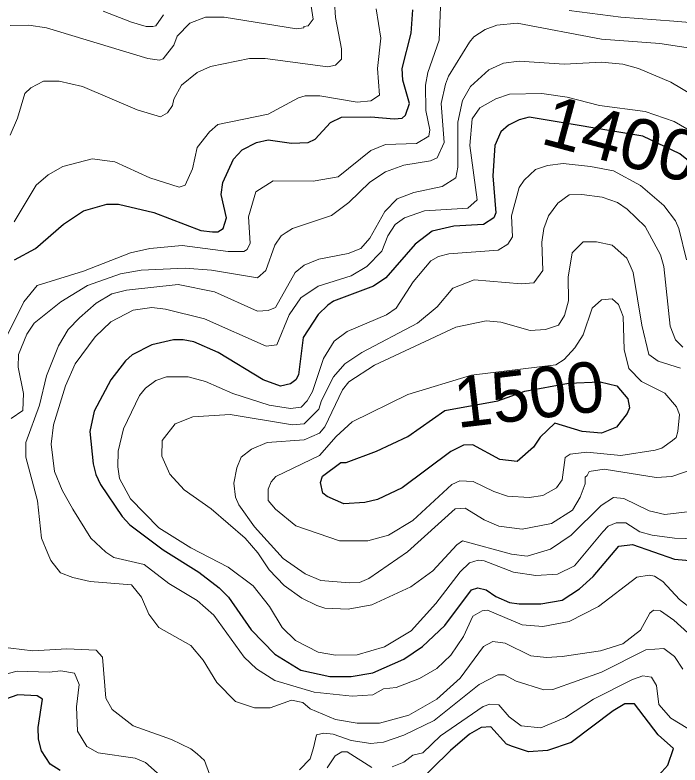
# Model space of a CAD drawing. Extents: x 423 to 448.8, y 7456.3 to 7484.
# Drawn here: x 432.428 to 433.481, y 7473.139 to 7474.327 of the extents above; entities that cross this region are included whole.
import ezdxf
from ezdxf.enums import TextEntityAlignment as Align

# ---------------------------------------------------------------- set-up
doc = ezdxf.new("R2010")
doc.units = 0
doc.header["$LTSCALE"] = 0.032
doc.layers.add('1', color=7, linetype='Continuous', lineweight=25)
doc.layers.add('2', color=7, linetype='Continuous', lineweight=13)
doc.layers.add('61', color=7, linetype='Continuous')

msp = doc.modelspace()

# ---------------------------------------------------------------- linework, layer by layer
at = {"layer": '1'}
for points in [[(432.741, 7473.9835), (432.7495, 7473.9835), (432.758, 7473.9889), (432.7634, 7474.0059), (432.7549, 7474.0431), (432.7572, 7474.0616), (432.7743, 7474.0987), (432.7882, 7474.1134), (432.8106, 7474.125), (432.8292, 7474.1297), (432.8663, 7474.1242), (432.8926, 7474.125), (432.9034, 7474.1304), (432.9281, 7474.1567), (432.9452, 7474.1653), (432.9916, 7474.166), (433.0287, 7474.1629), (433.0411, 7474.1637), (433.0465, 7474.1683), (433.0527, 7474.1869), (433.0426, 7474.224), (433.0411, 7474.2426), (433.0558, 7474.2983), (433.0581, 7474.3354)], [(433.4974, 7474.0941), (433.4812, 7474.1072), (433.4226, 7474.1353), (433.2422, 7474.1653), (433.2267, 7474.1614), (433.2097, 7474.1529), (433.1973, 7474.142), (433.188, 7474.1204), (433.1849, 7474.0725), (433.1896, 7474.0137), (433.1865, 7474.0059), (433.1703, 7473.9951), (433.1231, 7473.9928), (433.0891, 7473.985), (433.062, 7473.9642), (433.0156, 7473.9108), (432.9962, 7473.8976), (432.9328, 7473.8736), (432.9235, 7473.8675), (432.9081, 7473.8528), (432.8848, 7473.8164), (432.8771, 7473.7569), (432.8732, 7473.7491), (432.8647, 7473.743), (432.8485, 7473.7391), (432.8214, 7473.7491), (432.7502, 7473.7924), (432.7116, 7473.8095), (432.6946, 7473.8126), (432.6791, 7473.8126), (432.6451, 7473.8048), (432.6141, 7473.7886), (432.6033, 7473.7793), (432.5801, 7473.7491), (432.5538, 7473.6996), (432.5468, 7473.6672), (432.5523, 7473.6161), (432.5561, 7473.5991), (432.5639, 7473.5836), (432.5979, 7473.5326), (432.6103, 7473.5194), (432.6629, 7473.48), (432.7193, 7473.4444), (432.7518, 7473.4196), (432.7665, 7473.4049), (432.8021, 7473.3531), (432.84, 7473.3145), (432.881, 7473.2889), (432.9266, 7473.2789), (432.9607, 7473.2789), (432.9947, 7473.2851), (433.0442, 7473.3067), (433.0736, 7473.3268), (433.1091, 7473.3601), (433.1509, 7473.4165), (433.161, 7473.4196), (433.1741, 7473.4165), (433.1896, 7473.4057), (433.2113, 7473.3964), (433.2267, 7473.3941), (433.2608, 7473.3941), (433.2948, 7473.4003), (433.3219, 7473.4181), (433.3435, 7473.4374), (433.3845, 7473.4854), (433.4062, 7473.4885), (433.4727, 7473.4653), (433.5392, 7473.4591)], [(432.4277, 7473.9394), (432.461, 7473.9572), (432.5051, 7473.9958), (432.5368, 7474.0167), (432.5739, 7474.0276), (432.5925, 7474.0276), (432.6482, 7474.0144), (432.7224, 7473.9858), (432.741, 7473.9835)], [(432.4997, 7473.1304), (432.4842, 7473.1404), (432.4703, 7473.1613), (432.4656, 7473.1799), (432.4649, 7473.1984), (432.4718, 7473.2433), (432.4633, 7473.2487), (432.4331, 7473.2502), (432.4038, 7473.2402), (432.3295, 7473.2356), (432.311, 7473.2309), (432.2846, 7473.2177), (432.2615, 7473.1892), (432.2444, 7473.152), (432.2305, 7473.1334)], [(433.4479, 7473.1226), (433.4619, 7473.1389), (433.4711, 7473.1652), (433.4464, 7473.1868), (433.4093, 7473.2356), (433.3938, 7473.2356), (433.3752, 7473.2247), (433.3087, 7473.1744), (433.2716, 7473.1621), (433.2414, 7473.1598), (433.2159, 7473.1682), (433.2066, 7473.1721), (433.1818, 7473.1992), (433.1664, 7473.1984), (433.1478, 7473.1876), (433.1177, 7473.1621), (433.0589, 7473.104)]]:
    msp.add_lwpolyline(points, dxfattribs=at)
msp.add_lwpolyline([(433.0504, 7473.6594), (433.1091, 7473.7004), (433.1926, 7473.7159), (433.2357, 7473.731), (433.3049, 7473.744), (433.3549, 7473.7461), (433.3813, 7473.7396), (433.3984, 7473.719), (433.4015, 7473.705), (433.3977, 7473.6958), (433.3806, 7473.6741), (433.3567, 7473.6648), (433.3265, 7473.6671), (433.2832, 7473.6803), (433.26, 7473.6586), (433.2491, 7473.6424), (433.2236, 7473.6199), (433.1958, 7473.623), (433.1532, 7473.6462), (433.1386, 7473.6455), (433.1185, 7473.6354), (433.0411, 7473.5782), (433.0024, 7473.5596), (432.9823, 7473.555), (432.949, 7473.5526), (432.9228, 7473.5643), (432.9158, 7473.5697), (432.9119, 7473.5867), (432.915, 7473.5968), (432.9444, 7473.6184), (432.9529, 7473.6184), (433.0009, 7473.6362)], close=True, dxfattribs=at)
at = {"layer": '2'}
for points in [[(432.4208, 7474.3107), (432.4502, 7474.3114), (432.478, 7474.3068), (432.6389, 7474.2581), (432.6574, 7474.2557), (432.6629, 7474.258), (432.6799, 7474.2797), (432.6853, 7474.2937), (432.7054, 7474.3145), (432.7302, 7474.3238), (432.7596, 7474.3238), (432.874, 7474.3052), (432.8856, 7474.3068), (432.8856, 7474.3091), (432.8926, 7474.3099), (432.9003, 7474.3207), (432.888, 7474.4035)], [(432.4208, 7474.1366), (432.4324, 7474.1637), (432.444, 7474.2031), (432.4532, 7474.2116), (432.4734, 7474.2225), (432.4981, 7474.2225), (432.5353, 7474.214), (432.6219, 7474.1768), (432.659, 7474.166), (432.6698, 7474.1722), (432.6776, 7474.1838), (432.6799, 7474.1939), (432.6922, 7474.2163), (432.717, 7474.2364), (432.7379, 7474.2457), (432.7998, 7474.2581), (432.8245, 7474.2581), (432.9235, 7474.2449), (432.9359, 7474.248), (432.9452, 7474.2573), (432.9452, 7474.2736), (432.9359, 7474.3231), (432.9328, 7474.3726)], [(432.6636, 7474.3277), (432.6512, 7474.3099), (432.6466, 7474.3091), (432.6358, 7474.3091), (432.6126, 7474.3161), (432.5678, 7474.3331)], [(432.6111, 7473.9502), (432.642, 7473.9572), (432.6931, 7473.9618), (432.7658, 7473.9525), (432.7905, 7473.9525), (432.7959, 7473.9556), (432.8005, 7473.9657), (432.7982, 7474.0075), (432.8098, 7474.0469), (432.8369, 7474.0647), (432.9003, 7474.0639), (432.9398, 7474.0709), (432.9916, 7474.1126), (433.0148, 7474.1219), (433.0643, 7474.1235), (433.0836, 7474.1351), (433.0852, 7474.1452), (433.079, 7474.1761), (433.0782, 7474.2163), (433.0821, 7474.2364), (433.0999, 7474.2875), (433.1022, 7474.3401)], [(432.97, 7474.1892), (432.9916, 7474.1915), (433.0055, 7474.2), (433.0024, 7474.2426), (433.0078, 7474.2906), (433.0001, 7474.337)], [(433.3056, 7474.3346), (433.3876, 7474.3238), (433.4712, 7474.3176), (433.5547, 7474.3107)], [(433.1912, 7474.3114), (433.1726, 7474.3044), (433.1548, 7474.2929), (433.1478, 7474.2843), (433.1146, 7474.2302), (433.1099, 7474.2179), (433.103, 7474.1869), (433.1076, 7474.125), (433.0968, 7474.101), (433.086, 7474.0964), (433.0442, 7474.0895), (433.0148, 7474.0786), (432.9901, 7474.0624), (432.9568, 7474.0299), (432.9297, 7474.0098), (432.8679, 7473.9889), (432.8578, 7473.9827), (432.85, 7473.9773), (432.84, 7473.9626), (432.8253, 7473.9224), (432.8121, 7473.9108), (432.7395, 7473.9231), (432.6977, 7473.9262), (432.6281, 7473.9231), (432.5956, 7473.917), (432.543, 7473.8984), (432.5012, 7473.8729), (432.4587, 7473.8389), (432.4471, 7473.8218), (432.4339, 7473.7894), (432.4332, 7473.7693), (432.4416, 7473.7275), (432.4409, 7473.7004), (432.4223, 7473.688)], [(433.5114, 7474.2727), (433.4495, 7474.282), (433.3567, 7474.289), (433.2236, 7474.3145), (433.1912, 7474.3114)], [(433.5005, 7474.2008), (433.4665, 7474.2209), (433.4155, 7474.2426), (433.3907, 7474.2495), (433.3567, 7474.2527), (433.2979, 7474.2496), (433.2267, 7474.2542), (433.202, 7474.2511), (433.1788, 7474.2403), (433.1494, 7474.214), (433.137, 7474.1916), (433.1293, 7474.1575), (433.1293, 7474.0864), (433.1262, 7474.0693), (433.1045, 7474.0554), (433.0597, 7474.0461), (433.0334, 7474.0361), (433.014, 7474.016), (432.99, 7473.9734), (432.9761, 7473.9572), (432.956, 7473.9494), (432.9096, 7473.9402), (432.8864, 7473.9309), (432.8717, 7473.9193), (432.8408, 7473.8636), (432.8292, 7473.8589), (432.8121, 7473.8582), (432.7441, 7473.8884), (432.6869, 7473.9), (432.6049, 7473.8915), (432.5817, 7473.8853), (432.5569, 7473.8705), (432.5306, 7473.8473), (432.5128, 7473.8288), (432.4973, 7473.8033), (432.478, 7473.7553), (432.4672, 7473.7089), (432.4455, 7473.6501), (432.4455, 7473.6269), (432.4641, 7473.5573), (432.4703, 7473.4985), (432.4803, 7473.4738), (432.485, 7473.463), (432.5004, 7473.4436), (432.5198, 7473.4359), (432.5476, 7473.4297), (432.6126, 7473.4243), (432.6288, 7473.4049), (432.6404, 7473.3779), (432.6559, 7473.357), (432.707, 7473.3283), (432.7263, 7473.3052), (432.748, 7473.2696), (432.7773, 7473.2394), (432.8075, 7473.2293), (432.8323, 7473.2293), (432.8663, 7473.2417), (432.8841, 7473.2379), (432.8957, 7473.2278), (432.9359, 7473.2108), (432.97, 7473.2054), (433.0055, 7473.2054), (433.0519, 7473.2177), (433.096, 7473.2433), (433.1331, 7473.2765), (433.1702, 7473.3268), (433.185, 7473.3346), (433.2043, 7473.3322), (433.2453, 7473.3121), (433.2701, 7473.309), (433.2948, 7473.3106), (433.3551, 7473.3198), (433.3907, 7473.3307), (433.4186, 7473.3523), (433.4332, 7473.3794), (433.4394, 7473.384), (433.4502, 7473.3833), (433.4712, 7473.3686), (433.5214, 7473.3229)], [(432.4269, 7473.9997), (432.4618, 7474.0577), (432.4811, 7474.074), (432.5043, 7474.0871), (432.5507, 7474.0995), (432.5863, 7474.0948), (432.642, 7474.0694), (432.6884, 7474.0546), (432.6977, 7474.0577), (432.7093, 7474.0833), (432.717, 7474.1173), (432.7363, 7474.142), (432.7495, 7474.1536), (432.8292, 7474.1699), (432.8771, 7474.1962), (432.888, 7474.1993), (432.9112, 7474.1993), (432.97, 7474.1892)], [(433.5021, 7474.1413), (433.4721, 7474.1587), (433.4263, 7474.1745), (433.3536, 7474.1838), (433.3025, 7474.1969), (433.2623, 7474.2031), (433.2113, 7474.2016), (433.1896, 7474.1946), (433.1641, 7474.1799), (433.1524, 7474.1629), (433.1486, 7474.1204), (433.1602, 7474.0345), (433.1455, 7474.0214), (433.137, 7474.0206), (433.0767, 7474.0167), (433.045, 7474.0059), (433.0303, 7473.9951), (433.0186, 7473.9773), (433.0094, 7473.9533), (432.9854, 7473.9286), (432.9607, 7473.9139), (432.9081, 7473.8976), (432.881, 7473.8791), (432.8624, 7473.852), (432.8431, 7473.8048), (432.8261, 7473.8025), (432.7286, 7473.8458), (432.6668, 7473.8613), (432.6451, 7473.8636), (432.6157, 7473.8597), (432.5801, 7473.8412), (432.5553, 7473.8172), (432.5236, 7473.7746), (432.5082, 7473.7399), (432.4896, 7473.678), (432.4858, 7473.647), (432.4911, 7473.6037), (432.5028, 7473.5743), (432.5198, 7473.5442), (432.5484, 7473.4985), (432.5724, 7473.4761), (432.5848, 7473.4676), (432.6327, 7473.4567), (432.6721, 7473.4266), (432.717, 7473.3995), (432.7433, 7473.3763), (432.7913, 7473.3098), (432.8106, 7473.2912), (432.84, 7473.2727), (432.9019, 7473.2541), (432.9622, 7473.2479), (432.9947, 7473.2502), (433.0117, 7473.2595), (433.0318, 7473.2619), (433.069, 7473.2757), (433.096, 7473.292), (433.1184, 7473.3129), (433.1385, 7473.3423), (433.1532, 7473.3747), (433.168, 7473.3833), (433.1764, 7473.384), (433.2314, 7473.3608), (433.2639, 7473.3585), (433.3056, 7473.3662), (433.352, 7473.3903), (433.4131, 7473.4367), (433.4325, 7473.4397), (433.441, 7473.4382), (433.4541, 7473.4297), (433.4804, 7473.401), (433.5021, 7473.384)], [(433.4185, 7474.0569), (433.376, 7474.0802), (433.3397, 7474.0871), (433.2964, 7474.0918), (433.2716, 7474.0887), (433.2522, 7474.0825), (433.2344, 7474.0655), (433.2267, 7474.0538), (433.2144, 7474.009), (433.2159, 7473.9757), (433.2089, 7473.9642), (433.1934, 7473.9548), (433.1154, 7473.9487), (433.0991, 7473.9448), (433.0867, 7473.9378), (433.0589, 7473.9046), (433.0318, 7473.8628), (433.0163, 7473.852), (432.9545, 7473.8257), (432.9336, 7473.8102), (432.9166, 7473.7832), (432.8995, 7473.7306), (432.891, 7473.7159), (432.8817, 7473.7058), (432.8648, 7473.7035), (432.8307, 7473.7089), (432.7734, 7473.7274), (432.7302, 7473.7468), (432.7023, 7473.7538), (432.6683, 7473.7538), (432.6512, 7473.7483), (432.635, 7473.736), (432.6257, 7473.7244), (432.6002, 7473.6718), (432.5917, 7473.6362), (432.591, 7473.6115), (432.594, 7473.5929), (432.6111, 7473.5604), (432.6559, 7473.5148), (432.7069, 7473.4831), (432.7658, 7473.4521), (432.8052, 7473.4227), (432.8315, 7473.3903), (432.8516, 7473.357), (432.8725, 7473.3361), (432.9081, 7473.3175), (432.9359, 7473.3129), (432.97, 7473.3137), (433.0133, 7473.326), (433.0558, 7473.3516), (433.0945, 7473.3949), (433.1331, 7473.4451), (433.1478, 7473.4591), (433.1618, 7473.4637), (433.1711, 7473.4622), (433.2175, 7473.4444), (433.253, 7473.439), (433.2871, 7473.4413), (433.3141, 7473.4544), (433.359, 7473.5086), (433.3675, 7473.5171), (433.3799, 7473.5225), (433.3953, 7473.5225), (433.4178, 7473.5086), (433.4371, 7473.5031), (433.4727, 7473.4985), (433.5439, 7473.4962)], [(433.4913, 7473.9394), (433.4796, 7473.9889), (433.4742, 7474.0013), (433.4556, 7474.0252), (433.4185, 7474.0569)], [(433.2623, 7473.9673), (433.2654, 7473.9889), (433.2731, 7474.009), (433.2878, 7474.0291), (433.3056, 7474.0423), (433.3257, 7474.043), (433.3582, 7474.0384), (433.3822, 7474.0299), (433.3976, 7474.0198), (433.4263, 7473.992), (433.4502, 7473.9472), (433.4557, 7473.9286), (433.4657, 7473.8342), (433.4742, 7473.8126), (433.4858, 7473.8009)], [(432.9932, 7473.3925), (432.956, 7473.3856), (432.9189, 7473.3872), (432.9065, 7473.3918), (432.8825, 7473.4034), (432.8547, 7473.4235), (432.8307, 7473.4482), (432.8129, 7473.4753), (432.7928, 7473.4985), (432.7387, 7473.5449), (432.6961, 7473.5751), (432.6737, 7473.5998), (432.6606, 7473.6285), (432.6613, 7473.6532), (432.6822, 7473.6795), (432.71, 7473.6904), (432.7689, 7473.6942), (432.8679, 7473.6779), (432.8864, 7473.6795), (432.9096, 7473.7027), (432.9135, 7473.7167), (432.9328, 7473.7538), (432.9506, 7473.7747), (432.9776, 7473.7925), (433.0658, 7473.8388), (433.0968, 7473.8651), (433.1215, 7473.8945), (433.1556, 7473.9077), (433.2298, 7473.9015), (433.2499, 7473.903), (433.2638, 7473.9224), (433.2623, 7473.9673)], [(433.482, 7473.7677), (433.4464, 7473.7785), (433.4317, 7473.7894), (433.4208, 7473.8358), (433.4069, 7473.9193), (433.4023, 7473.9301), (433.3969, 7473.9417), (433.3737, 7473.9626), (433.3489, 7473.968), (433.328, 7473.968), (433.3103, 7473.9502), (433.304, 7473.9116), (433.3048, 7473.8744), (433.2986, 7473.8512), (433.2886, 7473.8358), (433.2685, 7473.8288), (433.2438, 7473.8272), (433.1973, 7473.8404), (433.1741, 7473.8427), (433.1262, 7473.8326), (432.9978, 7473.7723), (432.9568, 7473.746), (432.9467, 7473.7336), (432.9189, 7473.6749), (432.9104, 7473.6648), (432.8864, 7473.654), (432.8276, 7473.6501), (432.8029, 7473.6393), (432.7866, 7473.6269), (432.7796, 7473.6099), (432.775, 7473.5852), (432.7773, 7473.5635), (432.7828, 7473.5511), (432.8075, 7473.5163), (432.8531, 7473.4661), (432.888, 7473.442), (432.9127, 7473.4312), (432.9576, 7473.4274), (432.9738, 7473.4281), (432.9885, 7473.4343), (433.0496, 7473.4769), (433.1254, 7473.5449), (433.1409, 7473.5457), (433.1711, 7473.5271), (433.1943, 7473.5171), (433.2314, 7473.5125), (433.2778, 7473.5217), (433.311, 7473.5426), (433.3234, 7473.5635), (433.3311, 7473.5844), (433.3311, 7473.5952), (433.3342, 7473.5975), (433.3373, 7473.6037), (433.3613, 7473.6076), (433.4433, 7473.5944), (433.4681, 7473.596), (433.5036, 7473.6083)], [(432.41, 7473.8079), (432.4424, 7473.8729), (432.4633, 7473.8984), (432.5368, 7473.9216), (432.6111, 7473.9502)], [(433.5686, 7473.5488), (433.4572, 7473.5356), (433.4325, 7473.5418), (433.3923, 7473.5612), (433.376, 7473.5627), (433.3566, 7473.5503), (433.3087, 7473.5031), (433.2762, 7473.4807), (433.2391, 7473.4699), (433.2144, 7473.473), (433.137, 7473.4939), (433.1277, 7473.4877), (433.0898, 7473.4467), (433.055, 7473.4212), (432.9932, 7473.3925)], [(432.4038, 7473.326), (432.4564, 7473.3198), (432.5105, 7473.3229), (432.5569, 7473.3206), (432.5669, 7473.3098), (432.5724, 7473.2448), (432.5824, 7473.227), (432.6157, 7473.2007), (432.676, 7473.1791), (432.707, 7473.1644), (432.717, 7473.1566), (432.7286, 7473.1458), (432.7464, 7473.0971)], [(432.8787, 7473.1311), (432.8957, 7473.1489), (432.9011, 7473.166), (432.9057, 7473.1868), (432.9174, 7473.1892), (432.932, 7473.1876), (432.9607, 7473.1775), (432.9916, 7473.1729), (433.0117, 7473.1752), (433.0442, 7473.186), (433.0922, 7473.2092), (433.1633, 7473.2665), (433.1927, 7473.2819), (433.2035, 7473.2819), (433.2221, 7473.2719), (433.2654, 7473.258), (433.2801, 7473.2587), (433.3567, 7473.2858), (433.427, 7473.3214), (433.4557, 7473.3237), (433.4727, 7473.3106), (433.4858, 7473.2905)], [(432.6629, 7473.118), (432.635, 7473.1427), (432.6188, 7473.1497), (432.56, 7473.1582), (432.5422, 7473.1682), (432.5275, 7473.1923), (432.526, 7473.2309), (432.5298, 7473.2665), (432.5228, 7473.2843), (432.5012, 7473.2882), (432.4827, 7473.2858), (432.4316, 7473.2874), (432.3806, 7473.2742)], [(433.5206, 7473.1806), (433.4665, 7473.2131), (433.4479, 7473.2348), (433.4441, 7473.265), (433.4363, 7473.2781), (433.4224, 7473.2804), (433.4062, 7473.2742), (433.3443, 7473.2433), (433.3002, 7473.2139), (433.2608, 7473.1976), (433.2298, 7473.2007), (433.2105, 7473.2154), (433.1942, 7473.234), (433.1803, 7473.2355), (433.1695, 7473.2317), (433.1022, 7473.1853), (433.0743, 7473.1582), (433.0581, 7473.1543), (433.0442, 7473.1435), (433.0256, 7473.1358)], [(432.9932, 7473.135), (432.9544, 7473.1597), (432.9459, 7473.1597), (432.9351, 7473.1535), (432.9227, 7473.1342)]]:
    msp.add_lwpolyline(points, dxfattribs=at)
msp.add_lwpolyline([(433.478, 7473.6672), (433.4804, 7473.6942), (433.4758, 7473.7066), (433.4572, 7473.7282), (433.4201, 7473.7468), (433.4, 7473.7669), (433.393, 7473.7971), (433.3915, 7473.8497), (433.3837, 7473.8683), (433.3737, 7473.8775), (433.3567, 7473.876), (433.342, 7473.8628), (433.328, 7473.8203), (433.3149, 7473.8001), (433.2979, 7473.7816), (433.2847, 7473.7731), (433.1511, 7473.7567), (433.0504, 7473.7259), (432.9622, 7473.6826), (432.9367, 7473.6594), (432.9104, 7473.6292), (432.8416, 7473.596), (432.8338, 7473.5875), (432.8292, 7473.5759), (432.8292, 7473.5581), (432.8408, 7473.5442), (432.8732, 7473.5178), (432.9421, 7473.4939), (432.987, 7473.4939), (433.0195, 7473.5032), (433.0581, 7473.5264), (433.12, 7473.5836), (433.1324, 7473.589), (433.154, 7473.5883), (433.1865, 7473.572), (433.2082, 7473.5651), (433.2422, 7473.5627), (433.2639, 7473.5658), (433.2855, 7473.5782), (433.2948, 7473.5906), (433.2994, 7473.6261), (433.3072, 7473.6315), (433.3335, 7473.6346), (433.3876, 7473.6292), (433.4418, 7473.6378), (433.4526, 7473.6409), (433.4696, 7473.6532), (433.475, 7473.6578)], close=True, dxfattribs=at)

# ---------------------------------------------------------------- texts
at = {"layer": '61', "width": 1.05}
msp.add_text('1400', height=0.08, rotation=344.995, dxfattribs=at).set_placement((433.3788, 7474.0919), align=Align.CENTER)
at = {"layer": '61'}
msp.add_text('1500', height=0.08, rotation=6.774, dxfattribs=at).set_placement((433.2467, 7473.6867), align=Align.CENTER)

doc.saveas('drawing.dxf')
